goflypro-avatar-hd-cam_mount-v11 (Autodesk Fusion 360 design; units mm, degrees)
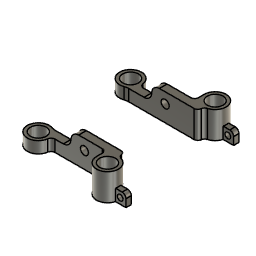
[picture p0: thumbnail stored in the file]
sketch "Skizze1" plane through (0, 0, 0) normal (0, 0, 1) x axis (1, 0, 0)
  line L1 (10, 2.5) -> (-8.6316, 2.5)
  line L2 (10, 0.85) -> (10, 2.5)
  line L3 (7.15, 0.5) -> (-7.1942, 0.5)
  line L4 (-2, 0.5) -> (-2, 2.5)
  line L5 (7.15, 0.5) -> (7.15, -2)
  circle C1 centre (-10, 0) radius 2.05
  circle C2 centre (10, -2) radius 2.05
  circle C3 centre (-10, 0) radius 2.85
  circle C4 centre (10, -2) radius 2.85
  point P5 (-2, 2.5)
  point P6 (-2, 0.5)
  point P8 (-8.6316, 2.5)
  point P9 (-7.1942, 0.5)
  point P11 (7.15, -2)
  point P13 (10, 0.85)
  perpendicular L1 L2
  coincident L1 P5
  coincident L3 P6
  concentric C1 C3
  coincident C3 P8
  coincident C3 P9
  coincident C4 P11
  tangent C4 L5
  perpendicular L3 L5
  coincident C4 P13
  dimension "d1" diameter C1 = 4.1
  dimension "d2" diameter C2 = 4.1
  dimension "d87" diameter C3 = 5.7
  dimension "d88" diameter C4 = 5.7
extrude "Extrusion1" new body sketch "Skizze1" profile of C2 L1 L2 L3 L4 along normal blind 7
extrude "Extrusion5" new body sketch "Skizze1" profile of C1 L1 L3 L4 C3 along normal blind 3 bodies "GoFlyPro - Avatar-HD-Cam mount - left"
combine "Kombinieren"
sketch "Skizze2" plane through (0, 0.5, 0) normal (0, 1, 0) x axis (1, 0, 0)
  line L1 (7.2, 0) -> (1, 0)
  line L2 (7.2, -7) -> (7.2, 0)
  line L3 (1, -7) -> (7.2, -7)
  line L4 (1, 0) -> (1, -7)
  line L5 (7.15, 0) -> (-7.1942, 0)
  line L6 (-7.1942, -3) -> (-2, -3)
  line L7 (-2, -7) -> (7.15, -7)
  line L8 (-2, -3) -> (-2, -7)
  line L9 (7.15, -7) -> (7.15, 0)
  line L10 (-7.1942, 0) -> (-7.1942, -3)
  circle C1 centre (1.5, -4.25) radius 1.05
  circle C2 centre (6.0963, -8.1067) radius 1.05
  circle C3 centre (1.5, -4.25) radius 4.95
  circle C4 centre (1.5, -4.25) radius 7.05
  circle C5 centre (1.5, -10.25) radius 1.05
  concentric C1 C3
  tangent C2 C3
  concentric C3 C4
  tangent C2 C4
  dimension "d8" diameter C1 = 2.1
  dimension "d31" diameter C2 = 2.1
  dimension "d32" diameter C5 = 2.1
extrude "Extrusion2" cut sketch "Skizze2" profile of C1 along normal blind 2
fillet "Abrundung13" radius 1
fillet "Abrundung14" radius 1
fillet "Abrundung15" radius 1
fillet "Abrundung16" radius 1
fillet "Abrundung17" radius 2
fillet "Abrundung18" radius 2
fillet "Abrundung19" radius 3
sketch "Skizze3" plane through (0, 0, 0) normal (0, 0, 1) x axis (1, 0, 0)
  line L1 (12.5, -2.7) -> (15.5, -2.7)
  line L2 (12.5, -1.3) -> (12.5, -2.7)
  line L3 (15.5, -1.3) -> (12.5, -1.3)
  line L4 (15.5, -2.7) -> (15.5, -1.3)
  horizontal L1
  vertical L2
  horizontal L3
  vertical L4
extrude "Extrusion8" add sketch "Skizze3" along normal blind 3
sketch "Skizze4" plane through (0, -2.7, 0) normal (0, -1, 0) x axis (1, 0, 0)
  line L1 (15.5, 0) -> (12.7627, 0)
  line L2 (15.5, 3) -> (15.5, 0)
  line L3 (12.7627, 3) -> (15.5, 3)
  line L4 (12.7627, 0) -> (12.7627, 3)
  circle C1 centre (14, 1.5) radius 0.75
  dimension "d82" diameter C1 = 1.5
extrude "Extrusion9" cut sketch "Skizze4" profile of C1 against normal blind 2
fillet "Abrundung20" radius 1
work_plane "Arbeitsebene" AlongDistance 12
mirror "Spiegeln" mirrorStitchTolerance 0.1 bodies "GoFlyPro - Avatar-HD-Cam mount - right"
named bodies: "GoFlyPro - Avatar-HD-Cam mount - left", "GoFlyPro - Avatar-HD-Cam mount - right"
